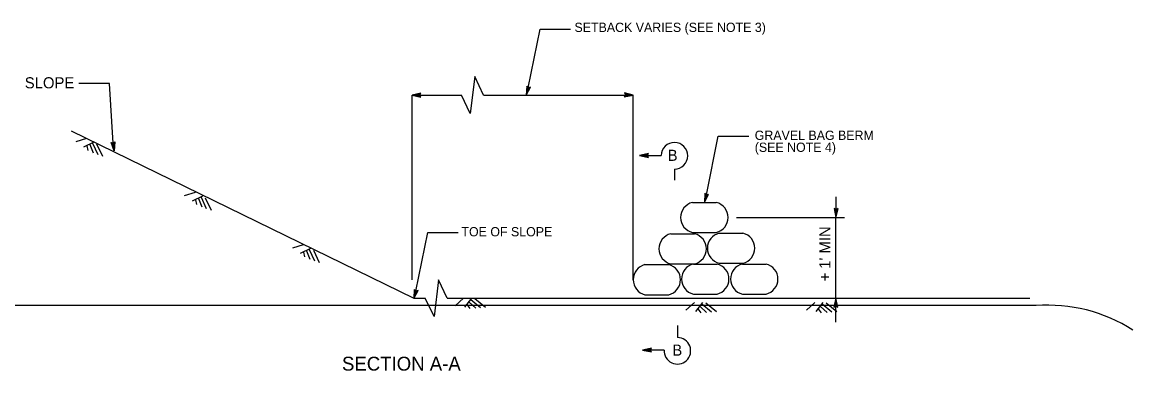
# Model space of a CAD drawing. Extents: x 6707406 to 6714471, y 1868570 to 1872341.
# Drawn here: x 6712375 to 6713095, y 1869972 to 1870198 of the extents above; entities that cross this region are included whole.
import ezdxf

# ---------------------------------------------------------------- set-up
doc = ezdxf.new("R2010")
doc.units = 0
for name, color, linetype in [('56 Stg 3 Anno', 7, 'Continuous'), ('57 Undefined', 7, 'Continuous'), ('59 Soundwall Ann', 7, 'Continuous'), ('G-SYMB', 7, 'Continuous'), ('G-TEXT', 7, 'Continuous')]:
    doc.layers.add(name, color=color, linetype=linetype)

msp = doc.modelspace()

# ---------------------------------------------------------------- linework, layer by layer
at = {"layer": '56 Stg 3 Anno'}
for p, q in [((6712702.1, 1870156.88), (6712701.84, 1870150.98)), ((6712701.84, 1870150.98), (6712704.57, 1870156.21)), ((6712703.14, 1870155.8), (6712702.1, 1870156.88)), ((6712702.1, 1870156.88), (6712702.1, 1870156.88)), ((6712702.37, 1870156.59), (6712702.18, 1870152.26)), ((6712702.19, 1870152.27), (6712704.18, 1870156.08)), ((6712702.65, 1870156.28), (6712702.53, 1870153.54)), ((6712702.53, 1870153.54), (6712703.81, 1870156.01)), ((6712702.92, 1870156.03), (6712702.87, 1870154.82)), ((6712702.87, 1870154.82), (6712703.42, 1870155.88)), ((6712704.57, 1870156.21), (6712703.14, 1870155.8)), ((6712704.57, 1870156.21), (6712704.57, 1870156.21)), ((6712633.63, 1870152.33), (6712627.84, 1870151.18)), ((6712627.84, 1870151.18), (6712627.84, 1870151.18)), ((6712627.84, 1870151.18), (6712633.57, 1870149.77)), ((6712633.42, 1870151.99), (6712629.17, 1870151.15)), ((6712629.18, 1870151.15), (6712633.35, 1870150.12)), ((6712633.19, 1870151.65), (6712630.5, 1870151.12)), ((6712630.5, 1870151.12), (6712633.19, 1870150.45)), ((6712633.01, 1870151.32), (6712631.82, 1870151.09)), ((6712631.82, 1870151.09), (6712632.98, 1870150.8)), ((6712632.83, 1870151.06), (6712633.63, 1870152.33)), ((6712633.57, 1870149.77), (6712632.83, 1870151.06)), ((6712633.57, 1870149.77), (6712633.57, 1870149.77)), ((6712633.63, 1870152.33), (6712633.63, 1870152.33)), ((6712701.84, 1870150.98), (6712701.84, 1870150.98)), ((6712766.08, 1870151.31), (6712765.28, 1870150.04)), ((6712765.28, 1870150.04), (6712771.07, 1870151.18)), ((6712765.28, 1870150.04), (6712765.28, 1870150.04)), ((6712771.07, 1870151.18), (6712765.34, 1870152.6)), ((6712765.34, 1870152.6), (6712765.34, 1870152.6)), ((6712765.34, 1870152.6), (6712766.08, 1870151.31)), ((6712765.49, 1870150.38), (6712769.74, 1870151.22)), ((6712769.73, 1870151.22), (6712765.56, 1870152.25)), ((6712768.42, 1870151.25), (6712765.72, 1870151.92)), ((6712765.73, 1870150.72), (6712768.42, 1870151.25)), ((6712765.9, 1870151.05), (6712767.09, 1870151.28)), ((6712767.09, 1870151.28), (6712765.94, 1870151.57)), ((6712771.07, 1870151.18), (6712771.07, 1870151.18)), ((6712434.87, 1870114.92), (6712432.88, 1870120.48)), ((6712432.88, 1870120.48), (6712432.88, 1870120.48)), ((6712432.88, 1870120.48), (6712434.24, 1870119.87)), ((6712434.7, 1870116.25), (6712433.25, 1870120.3)), ((6712434.54, 1870117.55), (6712433.6, 1870120.17)), ((6712434.37, 1870118.87), (6712433.97, 1870119.99)), ((6712434.24, 1870119.87), (6712435.42, 1870120.8)), ((6712434.48, 1870120.07), (6712434.37, 1870118.87)), ((6712434.79, 1870120.28), (6712434.54, 1870117.55)), ((6712435.11, 1870120.55), (6712434.7, 1870116.24)), ((6712435.42, 1870120.8), (6712434.87, 1870114.92)), ((6712435.42, 1870120.8), (6712435.42, 1870120.8)), ((6712434.87, 1870114.92), (6712434.87, 1870114.92)), ((6712780.97, 1870113.24), (6712775.2, 1870111.96)), ((6712775.2, 1870111.96), (6712775.2, 1870111.96)), ((6712775.2, 1870111.96), (6712780.97, 1870110.68)), ((6712775.2, 1870111.96), (6712789.14, 1870111.96)), ((6712780.76, 1870112.9), (6712776.53, 1870111.96)), ((6712776.54, 1870111.95), (6712780.74, 1870111.02)), ((6712780.53, 1870112.56), (6712777.86, 1870111.96)), ((6712777.86, 1870111.96), (6712780.57, 1870111.36)), ((6712780.36, 1870112.22), (6712779.18, 1870111.96)), ((6712779.18, 1870111.96), (6712780.35, 1870111.7)), ((6712780.2, 1870111.96), (6712780.97, 1870113.24)), ((6712780.97, 1870110.68), (6712780.2, 1870111.96)), ((6712780.97, 1870113.24), (6712780.97, 1870113.24)), ((6712780.97, 1870110.68), (6712780.97, 1870110.68)), ((6712797.76, 1870103.16), (6712797.76, 1870096.03)), ((6712817.41, 1870087.45), (6712817.16, 1870081.55)), ((6712817.16, 1870081.55), (6712819.89, 1870086.78)), ((6712817.16, 1870081.55), (6712817.16, 1870081.55)), ((6712818.45, 1870086.37), (6712817.41, 1870087.45)), ((6712817.41, 1870087.45), (6712817.41, 1870087.45)), ((6712817.69, 1870087.16), (6712817.5, 1870082.83)), ((6712817.51, 1870082.84), (6712819.5, 1870086.65)), ((6712817.96, 1870086.85), (6712817.84, 1870084.11)), ((6712817.84, 1870084.11), (6712819.13, 1870086.57)), ((6712818.24, 1870086.6), (6712818.19, 1870085.39)), ((6712818.19, 1870085.39), (6712818.74, 1870086.45)), ((6712819.89, 1870086.78), (6712818.45, 1870086.37)), ((6712819.89, 1870086.78), (6712819.89, 1870086.78)), ((6712902.55, 1870076.79), (6712901.29, 1870077.59)), ((6712901.29, 1870077.59), (6712901.29, 1870077.59)), ((6712901.29, 1870077.59), (6712902.43, 1870071.8)), ((6712901.62, 1870077.37), (6712902.46, 1870073.12)), ((6712901.96, 1870077.14), (6712902.49, 1870074.45)), ((6712902.29, 1870076.96), (6712902.53, 1870075.78)), ((6712902.43, 1870071.8), (6712903.85, 1870077.53)), ((6712902.47, 1870073.13), (6712903.5, 1870077.31)), ((6712902.49, 1870074.45), (6712903.16, 1870077.15)), ((6712902.53, 1870075.78), (6712902.81, 1870076.93)), ((6712903.85, 1870077.52), (6712902.55, 1870076.79)), ((6712903.85, 1870077.52), (6712903.85, 1870077.52)), ((6712902.43, 1870071.8), (6712902.43, 1870071.8)), ((6712629.32, 1870025.12), (6712629.07, 1870019.22)), ((6712629.07, 1870019.22), (6712631.8, 1870024.45)), ((6712630.37, 1870024.04), (6712629.32, 1870025.12)), ((6712629.32, 1870025.12), (6712629.32, 1870025.12)), ((6712629.6, 1870024.83), (6712629.41, 1870020.5)), ((6712629.42, 1870020.51), (6712631.41, 1870024.33)), ((6712629.87, 1870024.52), (6712629.76, 1870021.78)), ((6712629.76, 1870021.78), (6712631.04, 1870024.25)), ((6712630.15, 1870024.27), (6712630.1, 1870023.07)), ((6712630.1, 1870023.07), (6712630.65, 1870024.12)), ((6712631.8, 1870024.45), (6712630.37, 1870024.04)), ((6712631.8, 1870024.45), (6712631.8, 1870024.45)), ((6712629.07, 1870019.22), (6712629.07, 1870019.22)), ((6712902.43, 1870019.48), (6712901.11, 1870013.73)), ((6712902.42, 1870018.14), (6712901.46, 1870013.95)), ((6712902.41, 1870016.83), (6712901.79, 1870014.12)), ((6712902.99, 1870014.15), (6712902.41, 1870016.83)), ((6712903.33, 1870013.92), (6712902.42, 1870018.15)), ((6712903.67, 1870013.71), (6712902.43, 1870019.48)), ((6712902.43, 1870019.48), (6712902.43, 1870019.48)), ((6712901.11, 1870013.73), (6712902.39, 1870014.49)), ((6712901.11, 1870013.73), (6712901.11, 1870013.73)), ((6712902.4, 1870015.5), (6712902.14, 1870014.34)), ((6712902.39, 1870014.49), (6712903.67, 1870013.71)), ((6712902.66, 1870014.32), (6712902.4, 1870015.5)), ((6712903.67, 1870013.71), (6712903.67, 1870013.71)), ((6712799.7, 1870001.68), (6712799.7, 1869993.94)), ((6712782.91, 1869987.17), (6712777.14, 1869985.88)), ((6712777.14, 1869985.88), (6712777.14, 1869985.88)), ((6712777.14, 1869985.88), (6712782.9, 1869984.6)), ((6712791.07, 1869985.88), (6712777.14, 1869985.88)), ((6712782.7, 1869986.82), (6712778.47, 1869985.88)), ((6712778.48, 1869985.88), (6712782.68, 1869984.95)), ((6712782.47, 1869986.48), (6712779.8, 1869985.88)), ((6712779.8, 1869985.88), (6712782.51, 1869985.28)), ((6712782.3, 1869986.15), (6712781.12, 1869985.88)), ((6712781.12, 1869985.88), (6712782.28, 1869985.62)), ((6712782.14, 1869985.88), (6712782.91, 1869987.17)), ((6712782.9, 1869984.6), (6712782.14, 1869985.88)), ((6712782.9, 1869984.6), (6712782.9, 1869984.6)), ((6712782.91, 1869987.17), (6712782.91, 1869987.17))]:
    msp.add_line(p, q, dxfattribs=at)
for centre, start, end in [((6712797.75, 1870111.79), 270.04147, 178.88703), ((6712799.69, 1869985.36), 176.5025, 89.89451)]:
    msp.add_arc(centre, 8.62, start, end, dxfattribs=at)
at = {"layer": '59 Soundwall Ann'}
for p, q in [((6712417.03, 1870122.88), (6712409.97, 1870120.91)), ((6712421.68, 1870120.57), (6712415.1, 1870117.39)), ((6712417.12, 1870118.24), (6712417.83, 1870115.18)), ((6712419.19, 1870119.06), (6712421.29, 1870113.75)), ((6712420.9, 1870119.99), (6712424.22, 1870112.69)), ((6712423.56, 1870119.62), (6712427.28, 1870111.45)), ((6712487.41, 1870087.88), (6712480.35, 1870085.91)), ((6712492.06, 1870085.57), (6712485.48, 1870082.39)), ((6712487.5, 1870083.24), (6712488.21, 1870080.18)), ((6712489.57, 1870084.06), (6712491.67, 1870078.74)), ((6712491.28, 1870084.99), (6712494.6, 1870077.69)), ((6712493.94, 1870084.62), (6712497.66, 1870076.45)), ((6712557.38, 1870053.96), (6712550.32, 1870051.99)), ((6712562.03, 1870051.64), (6712555.45, 1870048.47)), ((6712557.47, 1870049.31), (6712558.18, 1870046.26)), ((6712559.54, 1870050.14), (6712561.64, 1870044.82)), ((6712561.25, 1870051.06), (6712564.57, 1870043.76)), ((6712563.92, 1870050.69), (6712567.63, 1870042.53)), ((6712661.24, 1870019.43), (6712655.76, 1870014.55)), ((6712666.43, 1870019.39), (6712661.91, 1870013.64)), ((6712664.85, 1870016.94), (6712669.08, 1870013.09)), ((6712665.98, 1870018.53), (6712672.17, 1870013.43)), ((6712668.54, 1870019.37), (6712675.46, 1870013.67)), ((6712810.75, 1870016.62), (6712805.27, 1870011.74)), ((6712815.95, 1870016.58), (6712811.43, 1870010.84)), ((6712818.05, 1870016.56), (6712824.98, 1870010.86)), ((6712888.79, 1870016.62), (6712883.31, 1870011.74)), ((6712893.99, 1870016.58), (6712889.47, 1870010.84)), ((6712896.1, 1870016.56), (6712903.02, 1870010.86)), ((6712663.35, 1870015.29), (6712665.33, 1870012.86)), ((6712812.87, 1870012.49), (6712814.85, 1870010.05)), ((6712814.37, 1870014.13), (6712818.6, 1870010.29)), ((6712815.5, 1870015.72), (6712821.69, 1870010.62)), ((6712890.91, 1870012.49), (6712892.89, 1870010.05)), ((6712892.41, 1870014.13), (6712896.64, 1870010.29)), ((6712893.54, 1870015.72), (6712899.73, 1870010.62))]:
    msp.add_line(p, q, dxfattribs=at)
at = {"layer": 'G-SYMB'}
for p, q in [((6712627.84, 1870031.46), (6712627.84, 1870151.18)), ((6712627.84, 1870151.18), (6712659.87, 1870151.18)), ((6712659.87, 1870151.18), (6712659.87, 1870151.18)), ((6712674.16, 1870151.18), (6712674.16, 1870151.18)), ((6712674.16, 1870151.18), (6712771.07, 1870151.18)), ((6712771.07, 1870031.46), (6712771.07, 1870151.18)), ((6712407.11, 1870127.93), (6712629.09, 1870019.43)), ((6712809.46, 1870081.55), (6712824.86, 1870081.55)), ((6712902.43, 1870085.24), (6712902.43, 1870071.8)), ((6712837.89, 1870071.8), (6712907.83, 1870071.8)), ((6712902.43, 1870017.46), (6712902.43, 1870071.8)), ((6712795.42, 1870061.23), (6712810.81, 1870061.23)), ((6712809.46, 1870062.05), (6712824.86, 1870062.05)), ((6712826.77, 1870061.63), (6712842.17, 1870061.63)), ((6712778.71, 1870041.22), (6712794.1, 1870041.22)), ((6712795.42, 1870041.73), (6712810.81, 1870041.73)), ((6712810.06, 1870041.62), (6712825.46, 1870041.62)), ((6712826.77, 1870042.13), (6712842.17, 1870042.13)), ((6712841.78, 1870041.62), (6712857.18, 1870041.62)), ((6712629.09, 1870019.43), (6712636.39, 1870019.43)), ((6712636.38, 1870019.46), (6712636.38, 1870019.46)), ((6712650.67, 1870019.46), (6712650.67, 1870019.46)), ((6712650.68, 1870019.43), (6713027.91, 1870019.43)), ((6712778.71, 1870021.71), (6712794.1, 1870021.71)), ((6712810.06, 1870022.11), (6712825.46, 1870022.11)), ((6712841.78, 1870022.11), (6712857.18, 1870022.11)), ((6712884.44, 1870019.42), (6712907.83, 1870019.42)), ((6712902.43, 1870004.02), (6712902.43, 1870017.46)), ((6713032, 1870014.67), (6712333.41, 1870014.67))]:
    msp.add_line(p, q, dxfattribs=at)
for points in [[(6712674.16, 1870151.18), (6712668.45, 1870163.11), (6712665.59, 1870139.26), (6712659.87, 1870151.18)], [(6712650.67, 1870019.46), (6712644.96, 1870031.38), (6712642.1, 1870007.54), (6712636.38, 1870019.46)]]:
    msp.add_lwpolyline(points, dxfattribs=at)
for points in [[(6712667.02, 1870151.18), (6712667.02, 1870151.18)], [(6712643.53, 1870019.46), (6712643.53, 1870019.46)]]:
    msp.add_lwpolyline(points, close=True, dxfattribs=at)
for centre, radius, start, end in [((6712811.86, 1870071.8), 10.04, 103.86547, 256.13453), ((6712822.45, 1870071.8), 10.04, 283.86547, 76.13453), ((6712797.82, 1870051.48), 10.04, 103.86547, 256.13453), ((6712808.41, 1870051.48), 10.04, 283.86547, 76.13453), ((6712829.18, 1870051.88), 10.04, 103.86547, 256.13453), ((6712839.76, 1870051.88), 10.04, 283.86547, 76.13453), ((6712781.11, 1870031.46), 10.04, 103.86547, 256.13453), ((6712791.7, 1870031.46), 10.04, 283.86547, 76.13453), ((6712812.47, 1870031.87), 10.04, 103.86547, 256.13453), ((6712823.05, 1870031.87), 10.04, 283.86547, 76.13453), ((6712844.19, 1870031.87), 10.04, 103.86547, 256.13453), ((6712854.77, 1870031.87), 10.04, 283.86547, 76.13453), ((6713039.61, 1869913.07), 101.88, 57.29579, 94.28514)]:
    msp.add_arc(centre, radius, start, end, dxfattribs=at)
at = {"layer": 'G-TEXT'}
for p, q in [((6712703.13, 1870155.81), (6712710.83, 1870193.88)), ((6712710.83, 1870193.88), (6712730.56, 1870193.88)), ((6712431.83, 1870158.65), (6712412.1, 1870158.65)), ((6712434.25, 1870119.88), (6712431.83, 1870158.65)), ((6712818.45, 1870086.37), (6712826.14, 1870124.45)), ((6712826.14, 1870124.45), (6712845.87, 1870124.45)), ((6712630.36, 1870024.05), (6712638.05, 1870062.12)), ((6712638.05, 1870062.12), (6712657.78, 1870062.12))]:
    msp.add_line(p, q, dxfattribs=at)

# ---------------------------------------------------------------- texts
at = {"layer": '57 Undefined'}
for p in [(6712793.39, 1870108.48), (6712796.4, 1869982.21)]:
    msp.add_text('B', height=7.21, dxfattribs=at).set_placement(p)
at = {"layer": 'G-SYMB'}
for s, p in [(" 1' MIN", (6712898.83, 1870035.88)), ('+', (6712898.83, 1870030.4))]:
    msp.add_text(s, height=7.2, rotation=90, dxfattribs=at).set_placement(p)
at = {"layer": 'G-TEXT'}
for s, height, p in [('SETBACK VARIES (SEE NOTE 3)', 6, (6712733.04, 1870192.06)), ('SLOPE', 7.2, (6712377, 1870155.5)), ('GRAVEL BAG BERM', 6, (6712849.8, 1870122.07)), ('(SEE NOTE 4)', 6, (6712849.8, 1870114.31)), ('TOE OF SLOPE', 6, (6712659.83, 1870059.56)), ('SECTION A-A', 9, (6712582.47, 1869972.53))]:
    msp.add_text(s, height=height, rotation=360, dxfattribs=at).set_placement(p)

doc.saveas('drawing.dxf')
